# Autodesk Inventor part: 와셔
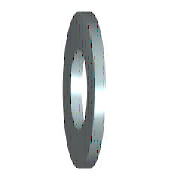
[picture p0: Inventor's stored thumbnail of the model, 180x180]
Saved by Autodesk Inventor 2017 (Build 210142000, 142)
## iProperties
Created: 2012-02
Part Number: 와셔
Material: 스테인리스강
Description: 평면 와셔 - 대형 시리즈 - 제품 등급 A
Document SubType Name: Modeling
Standard: ISO 7093 A
Designer: mduedu
Standard Revision: First Edition 2000-06-01
Standards Organization: ISO
Language: ko-KR
Size Designation: ST 3 - 140 HV - A
Categories: <MemberInstance><Categories><Category DisplayName="조임쇠" InternalName="e4da775c-781d-43d5-af7c-5136215cf5a6" Mnemonic="FSTN"><Category DisplayName="와셔" InternalN
Density: 8.08 g/cm^3
Mass: 0.359235 g
Surface Area: 1.41811 cm^2
Volume: 0.0444598 cm^3
Appearance: 파란색 - 벽 페인트 - 광택
IsCustomPart: 1
Author: mduedu
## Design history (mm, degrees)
sketch "스케치"
  geometry: C1 r 4.5 at (0, 0); C2 r 1.6 at (0, 0); 1 further point
  constraints: 2 centre point, 2 coincident
  dimensions: "d0" = 3.2 diameter of C2 (= SD1); "d1" = 9 diameter of C1 (= SD2)
extrude "본체" new body sketch "스케치" distance "d2" = 0.8 (= SD); taper "d3" = 0 deg
workaxis "Work Axis1"
workplane "Work Plane1"
sketch "스케치5"
  geometry: 2 further points
  constraints: 1 coincident
body "Solid1"
other parameters: "SD1" = 3.2 [user parameter; used in 1 equation term], "SD2" = 9 [user parameter; used in 1 equation term], "SD" = 0.8 [user parameter; used in 1 equation term], "d4" = 0, "d5" = 0, "d6" = 0, "d7" = 0, "NND" = 3 [user parameter]
